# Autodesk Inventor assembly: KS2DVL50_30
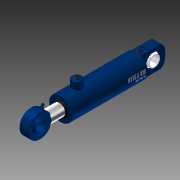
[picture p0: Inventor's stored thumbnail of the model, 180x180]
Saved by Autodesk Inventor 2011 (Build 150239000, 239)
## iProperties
Created: 2010-11
Document SubType Name: Assembly
Designer: TB
Mass: 566.294 g
Surface Area: 1153.75 cm^2
Volume: 566.294 cm^3
Density: 1 g/cm^3
Description: KS2DVL 50/30 - 100 mm
Slaglengde: 100,000 mm
Author: TB
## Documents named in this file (6)
- C:\Vault\Sylinderteknikk\Projects_ST\3D.nettkatalog\KS2-Series\KS2DVL\KS2DVL50_30\KS2DVL50_30.iam
- C:\Vault\Sylinderteknikk\Projects_ST\3D.nettkatalog\KS2-Series\KS2DVL\KS2DVL50_30\KS2DVL50_30_stang.ipt
- C:\Vault\Sylinderteknikk\Projects_ST\3D.nettkatalog\KS2-Series\KS2DVL\KS2DVL50_30\KS2DVL50_30_Parameters.ipt
- C:\Vault\Sylinderteknikk\Projects_ST\3D.nettkatalog\KS2-Series\KS2DVL\KS2DVL50_30\KS2DVL50_30_body..ipt
- C:\Vault\Sylinderteknikk\Projects_ST\Øyer\Klinkby.KS.Øyer\KS.25.øye.komplett\KS.eye25.ipt
- C:\Vault\Sylinderteknikk\Projects_ST\Øyer\Klinkby.KS.Øyer\KS.25.øye.komplett\KS.25.kule.ipt
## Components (5 placed, 5 different names)
1. KS2DVL50_30_Parameters:3
2. KS2DVL50_30_stang:1 — Mate:1, FriMate:2, Mate:3, Insert:2
3. KS2DVL50_30_body.:1 — Mate:1, FriMate:2, Mate:3, Insert:1, Angle:1
4. KS.eye25:1 — Insert:2, Angle:1
5. KS.25.kule:1 — Insert:1
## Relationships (6: Mate 3, Insert 2, Angle 1)
- Mate:1: KS2DVL50_30_stang:1 ↔ KS2DVL50_30_body.:1
- FriMate:2 [Mate]: KS2DVL50_30_stang:1 ↔ KS2DVL50_30_body.:1
- Mate:3: KS2DVL50_30_stang:1 ↔ KS2DVL50_30_body.:1
- Insert:1: KS2DVL50_30_body.:1 ↔ KS.25.kule:1
- Insert:2: KS2DVL50_30_stang:1 ↔ KS.eye25:1
- Angle:1: KS2DVL50_30_body.:1 ↔ KS.eye25:1
## Named parameters: Forlengelse_rør = 0, Vinkel_Minusport = 0
